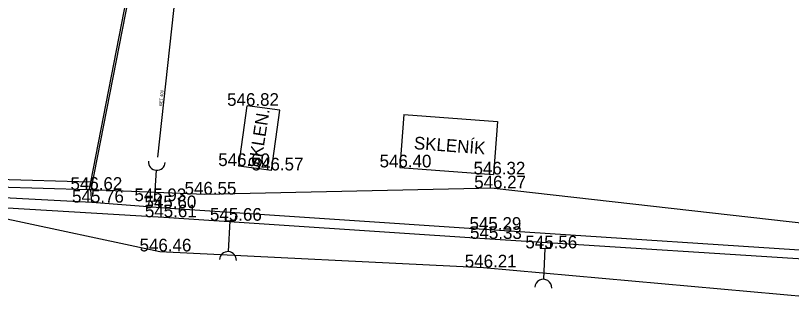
# Model space of a CAD drawing. Extents: x -669995 to -669686, y -1125551 to -1125263.
# Drawn here: x -669816.2 to -669770.25, y -1125374.98 to -1125358.09 of the extents above; entities that cross this region are included whole.
import ezdxf

# ---------------------------------------------------------------- set-up
doc = ezdxf.new("R2010")
doc.units = 0
for name, color, linetype in [('G_Bod_tecka', 7, 'Continuous'), ('G_Bod_vyska', 7, 'Continuous'), ('G_Breh_Teren', 7, 'Continuous'), ('G_Cesty_Schody', 7, 'Continuous'), ('G_Plochy_zpevnene', 7, 'Continuous'), ('G_Ploty', 7, 'Continuous'), ('G_Poznamky_odkaz', 7, 'Continuous'), ('G_Site-kanalizace', 7, 'Continuous'), ('G_Z_KANAL_podz_priblizne', 7, 'Continuous'), ('Vrstva 17', 7, 'Continuous'), ('Vrstva 3', 7, 'Continuous')]:
    doc.layers.add(name, color=color, linetype=linetype)

msp = doc.modelspace()

# ---------------------------------------------------------------- linework, layer by layer
at = {"layer": 'G_Bod_tecka'}
for p, q in [((-669802.49, -1125363.44), (-669802.49, -1125363.44)), ((-669802.98, -1125367.01), (-669802.98, -1125367.01)), ((-669801.04, -1125367.27), (-669801.04, -1125367.27)), ((-669793.44, -1125367.09), (-669793.44, -1125367.09)), ((-669787.9, -1125367.51), (-669787.9, -1125367.51)), ((-669811.75, -1125368.42), (-669811.75, -1125368.42)), ((-669805.01, -1125368.7), (-669805.01, -1125368.7)), ((-669787.86, -1125368.33), (-669787.86, -1125368.33)), ((-669811.67, -1125369.18), (-669811.67, -1125369.18)), ((-669807.99, -1125369.09), (-669807.99, -1125369.09)), ((-669807.36, -1125369.51), (-669807.36, -1125369.51)), ((-669807.42, -1125370.05), (-669807.42, -1125370.05)), ((-669803.49, -1125370.25), (-669803.49, -1125370.25)), ((-669788.15, -1125370.79), (-669788.15, -1125370.79)), ((-669788.12, -1125371.33), (-669788.12, -1125371.33)), ((-669784.83, -1125371.89), (-669784.83, -1125371.89)), ((-669807.66, -1125372.07), (-669807.66, -1125372.07)), ((-669788.48, -1125373.02), (-669788.48, -1125373.02))]:
    msp.add_line(p, q, dxfattribs=at)
at = {"layer": 'G_Breh_Teren'}
for p, q in [((-669805.01, -1125368.7), (-669811.74, -1125368.42)), ((-669787.86, -1125368.33), (-669805.01, -1125368.7)), ((-669787.86, -1125368.33), (-669766.63, -1125370.72)), ((-669818.37, -1125369.78), (-669807.66, -1125372.07)), ((-669807.66, -1125372.07), (-669788.48, -1125373.02)), ((-669788.48, -1125373.02), (-669766.79, -1125374.98))]:
    msp.add_line(p, q, dxfattribs=at)
for points in [[(-669749.78, -1125373.18), (-669766.46, -1125372.21), (-669788.15, -1125370.79), (-669807.36, -1125369.51), (-669811.67, -1125369.18)], [(-669818.35, -1125369.39), (-669807.42, -1125370.05), (-669788.12, -1125371.33), (-669766.46, -1125372.7), (-669749.86, -1125374)]]:
    msp.add_lwpolyline(points, dxfattribs=at)
at = {"layer": 'G_Cesty_Schody'}
for p, q in [((-669802.98, -1125367.01), (-669802.49, -1125363.44)), ((-669800.55, -1125363.7), (-669802.49, -1125363.44)), ((-669801.04, -1125367.27), (-669800.55, -1125363.7)), ((-669793.2, -1125363.95), (-669793.44, -1125367.09)), ((-669793.2, -1125363.95), (-669787.66, -1125364.37)), ((-669787.66, -1125364.37), (-669787.9, -1125367.51)), ((-669801.04, -1125367.27), (-669802.98, -1125367.01)), ((-669793.44, -1125367.09), (-669787.9, -1125367.51))]:
    msp.add_line(p, q, dxfattribs=at)
at = {"layer": 'G_Plochy_zpevnene'}
for p, q in [((-669811.85, -1125368.42), (-669818.22, -1125368.23)), ((-669811.74, -1125368.42), (-669811.85, -1125368.42)), ((-669811.67, -1125369.18), (-669811.74, -1125368.42)), ((-669811.67, -1125369.18), (-669818.29, -1125368.83))]:
    msp.add_line(p, q, dxfattribs=at)
at = {"layer": 'G_Ploty'}
for p, q in [((-669808.44, -1125350.97), (-669811.76, -1125367.96)), ((-669808.34, -1125350.98), (-669811.74, -1125368.42)), ((-669811.76, -1125367.96), (-669818.21, -1125367.78)), ((-669811.76, -1125367.96), (-669811.85, -1125368.42))]:
    msp.add_line(p, q, dxfattribs=at)
at = {"layer": 'G_Site-kanalizace'}
for p, q in [((-669807.863, -1125367.257), (-669807.99, -1125369.09)), ((-669808.31, -1125369.368), (-669808.289, -1125369.069)), ((-669808.289, -1125369.069), (-669807.99, -1125369.09)), ((-669807.691, -1125369.111), (-669807.99, -1125369.09)), ((-669807.712, -1125369.41), (-669807.691, -1125369.111)), ((-669803.773, -1125369.934), (-669803.79, -1125370.233)), ((-669803.174, -1125369.967), (-669803.19, -1125370.267)), ((-669803.79, -1125370.233), (-669803.49, -1125370.25)), ((-669803.593, -1125372.084), (-669803.49, -1125370.25)), ((-669803.19, -1125370.267), (-669803.49, -1125370.25)), ((-669785.115, -1125371.575), (-669785.13, -1125371.875)), ((-669785.13, -1125371.875), (-669784.83, -1125371.89)), ((-669784.922, -1125373.725), (-669784.83, -1125371.89)), ((-669784.53, -1125371.905), (-669784.83, -1125371.89)), ((-669784.515, -1125371.605), (-669784.53, -1125371.905))]:
    msp.add_line(p, q, dxfattribs=at)
for centre, start, end in [((-669807.828, -1125366.759), 176.0234, 356.0234), ((-669803.621, -1125372.583), 356.7845, 176.7845), ((-669784.947, -1125374.224), 357.1192, 177.1192)]:
    msp.add_arc(centre, 0.5, start, end, dxfattribs=at)
at = {"layer": 'G_Z_KANAL_podz_priblizne'}
msp.add_lwpolyline([(-669805.95, -1125304.06), (-669803.92, -1125330.96), (-669807.79, -1125366.49)], dxfattribs=at)
at = {"layer": 'Vrstva 17'}
msp.add_lwpolyline([(-669805.95, -1125304.06), (-669803.92, -1125330.96), (-669807.79, -1125366.49)], dxfattribs=at)

# ---------------------------------------------------------------- texts
at = {"layer": 'G_Bod_vyska'}
for s, p in [('546.82', (-669803.668, -1125363.44)), ('546.60', (-669804.193, -1125367.01)), ('546.40', (-669794.639, -1125367.09)), ('546.57', (-669802.218, -1125367.27)), ('546.32', (-669789.078, -1125367.51)), ('546.62', (-669812.942, -1125368.42)), ('546.27', (-669789.038, -1125368.33)), ('546.55', (-669806.188, -1125368.7)), ('545.76', (-669812.848, -1125369.18)), ('545.93', (-669809.156, -1125369.09)), ('545.60', (-669808.559, -1125369.51)), ('545.61', (-669808.536, -1125370.05)), ('545.66', (-669804.682, -1125370.25)), ('545.29', (-669789.316, -1125370.79)), ('545.33', (-669789.284, -1125371.33)), ('546.46', (-669808.852, -1125372.07)), ('545.56', (-669786.008, -1125371.89)), ('546.21', (-669789.596, -1125373.02))]:
    msp.add_text(s, height=0.75, dxfattribs=at).set_placement(p)
at = {"layer": 'G_Poznamky_odkaz'}
for s, rotation, p in [('SKLEN.', 81.1066, (-669801.695, -1125367.184)), ('SKLENÍK', 355.6646, (-669792.629, -1125366.005))]:
    msp.add_text(s, height=0.75, rotation=rotation, dxfattribs=at).set_placement(p)
at = {"layer": 'Vrstva 3'}
msp.add_text('BET 400', height=0.1755, rotation=83.8106, dxfattribs=at).set_placement((-669807.53, -1125363.452))

doc.saveas('drawing.dxf')
